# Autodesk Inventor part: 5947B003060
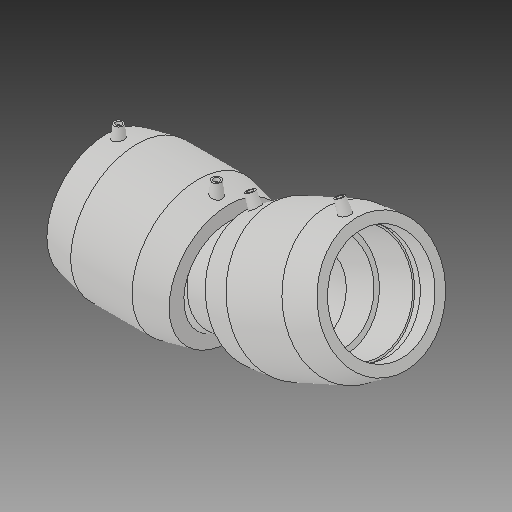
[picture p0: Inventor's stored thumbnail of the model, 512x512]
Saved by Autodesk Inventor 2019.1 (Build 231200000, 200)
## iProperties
Created: 2017-06
Part Number: 5947B003060
Material: Generic
Description: PLASSON ADJUSTABLE ELBOW ASTM 6''
Document SubType Name: Modeling
Designer: KIM
Mass: 16853.5 g
Surface Area: 12350.1 cm^2
Volume: 16853.5 cm^3
Density: 1 g/cm^3
Appearance: Default
Author: KIM
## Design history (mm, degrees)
derived "5947B.ipt"
feature "Solid1::5947B.ipt"
tag "TaggingFeature1"
body "Solid1"
other parameters: "d0" = 205.9432, "d2" = 223.012, "d3" = 102.87, "d4" = 51.435, "d5" = 200.7108, "d7" = 168, "d8" = 168 deg, "d10" = 41.148, "d11" = 13.716, "d29" = 125.984, "d30" = 15, "d31" = 82.37728, "d34" = 5 deg, "d41" = 4, "d42" = 14, "d43" = 0, "d48" = 151.2, "d49" = 24 deg, "d50" = 514.858, "d51" = 78 deg, "d52" = 90 deg, "d55" = 51.5366, "d57" = 168 deg, "d58" = 10.30732, "d60" = 60.74977, "d62" = 3, "d63" = 0, "d_" = 168, "L_" = 514.858, "L_1" = 102.87, "D_" = 223.012, "A_" = 125.984, "d54" = 103.0732, "d59" = 202.49924
